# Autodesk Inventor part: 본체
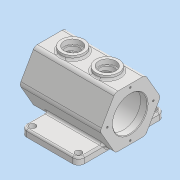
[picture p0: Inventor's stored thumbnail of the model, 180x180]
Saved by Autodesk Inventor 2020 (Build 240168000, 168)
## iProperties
Created: 2021-06
Part Number: 본체
Material: 일반
Document SubType Name: Modeling
Designer: Administrator
Density: 1 g/cm^3
Appearance: 기본값
Author: Administrator
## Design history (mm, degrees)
sketch "스케치1"
  geometry: L1 (52.5, 0)-(26.25, -45.466); L2 (26.25, -45.466)-(-26.25, -45.466); L3 (-26.25, -45.466)-(-52.5, 0); L4 (-52.5, 0)-(-26.25, 45.466); L5 (-26.25, 45.466)-(26.25, 45.466); L6 (26.25, 45.466)-(52.5, 0); 3 further points
  constraints: 12 end point, 1 coincident, 1 midpoint, 1 vertical alignment, 13 other
  dimensions: "d0" = 52.5 distance of L1.start point (0, 0)
extrude "돌출1" new body sketch "스케치1" stored distance "d1" = 140; taper "d2" = 0 deg
node "작업 평면1"
sketch "스케치2"
  geometry: L1 (-45, -75)-(55, -75); L2 (55, -75)-(55, 75); L3 (55, 75)-(-45, 75); L4 (-45, 75)-(-45, -75); L5 (-70, 26.25)-(-70, 52.5) reference; L6 (70, 52.5)-(70, 26.25) reference; 2 further points
  constraints: 8 end point, 2 parallel, 1 horizontal, 1 horizontal alignment, 1 midpoint, 1 perpendicular
  dimensions: "d4" = 150 distance of L1.end L2.end; "d5" = 25 distance between parallel lines of L4 L5; "d6" = 100 distance of L2.end L3.end
extrude "돌출2" join sketch "스케치2" distance "d7" = 12; taper "d8" = 0 deg
sketch "스케치3"
  geometry: L1 (70, 45.466)-(70, 0) reference; L2 (-70, 0)-(-70, 45.466) reference; L3 (70, 30)-(-70, 30); L4 (-70, 30)-(-70, 0); L5 (-70, 0)-(70, 0); L6 (70, 0)-(70, 30); L7 (58, 37.5)-(-58, 37.5); L8 (-58, 37.5)-(-58, 30); L9 (-58, 30)-(58, 30); L10 (58, 30)-(58, 37.5); 6 further points
  constraints: 16 end point, 4 parallel, 3 point on line, 2 horizontal, 2 midpoint, 2 perpendicular, 1 coincident, 1 vertical alignment
  dimensions: "d9" = 60 diameter of L3 L5; "d10" = 75 diameter of L7 L5; "d11" = 12 distance between parallel lines of L10 L1
revolve "회전1" sketch "스케치3" stored, may be unused: angle "d12" = 90 deg
node "작업 평면2"
sketch "스케치4"
  geometry: L1 (-70, -26.25)-(-70, 26.25) reference; C1 r 20 at (-30, 0); C2 r 20 at (30, 0); 1 further point
  constraints: 2 centre point, 2 horizontal alignment, 1 equal radius
  dimensions: "d14" = 40 distance from line of C1.centre L1; "d15" = 60 distance of C2.centre C1.centre; "d16" = 40 diameter of C1
extrude "돌출3" join sketch "스케치4" stored distance "d17" = 52.5; taper "d18" = 0 deg
sketch "스케치5"
  geometry: C1 r 20 at (0, 0) reference; 2 further points
  constraints: 1 coincident
hole "구멍1" sketch "스케치5" at (0, 0) diameter "d19" = 25; stored, may be unused: countersink angle "d23" = 90 deg, drill point angle "d25" = 118 deg; dims "d20" = 6, "d21" = 30, "d22" = 8, "d24" = 8
chamfer "모따기1" distance "d26" = 1; stored, may be unused: second distance "d27" = 2, angle "d28" = 45 deg
fillet "모깎기1" dims "d29" = 10, "d30" = 5, "d38" = 8
sketch "스케치6"
  geometry: A1 r 10 centre (-35, -65) between (-45, -65) and (-35, -75) reference; A2 r 10 centre (45, -65) between (45, -75) and (55, -65) reference; 3 further points
  constraints: 2 coincident
hole "구멍2" sketch "스케치6" at (-35, -65), (45, -65) diameter "d31" = 11; stored, may be unused: countersink angle "d35" = 90 deg, drill point angle "d37" = 118 deg; dims "d32" = 6, "d33" = 30, "d34" = 8, "d36" = 8
fillet "모깎기2" dims "d39" = 3
fillet "모깎기3" dims "d40" = 3
sketch "스케치7"
  geometry: L1 (0, 0)-(0, 40); C1 r 37.5 at (0, 0) reference; A1 r 40 centre (0, 0) between (0, 40) and (-40, 0); 1 further point
  constraints: 2 end point, 2 point on circle, 1 centre point, 1 coincident, 1 horizontal alignment, 1 vertical
  dimensions: "d41" = 80 diameter of A1
hole "구멍3" sketch "스케치7" at (-40, 0) diameter "d43" = 3.242; stored, may be unused: countersink angle "d47" = 90 deg, drill point angle "d49" = 118 deg; dims "d44" = 8, "d45" = 30, "d46" = 8, "d48" = 10
sketch "스케치8"
  geometry: L1 (0, 0)-(0, -40); L2 (0, 0)-(28.284, -28.284); L3 (40, 0)-(-40, 0); C1 r 30 at (0, 0) reference; C2 r 1.621 at (-40, 0) reference; A1 r 40 centre (0, 0) between (28.284, -28.284) and (0, -40); 3 further points
  constraints: 6 end point, 3 point on circle, 2 coincident, 1 centre point, 1 horizontal, 1 symmetric about line, 1 vertical
  dimensions: "d53" = 80 diameter of A1; "d54" = 45 deg angle of L2 L1
hole "구멍4" sketch "스케치8" at (28.284, -28.284), (28.284, 28.284) diameter "d55" = 3.242; stored, may be unused: countersink angle "d59" = 90 deg, drill point angle "d61" = 118 deg; dims "d56" = 8, "d57" = 30, "d58" = 8, "d60" = 10
sketch "스케치9"
  geometry: L1 (-45, 65)-(-45, 32.293) reference; L2 (45, 75)-(-35, 75) reference; 2 further points
  constraints: 1 other
  dimensions: "d65" = 50 distance from line of point (5, 61) L1; "d66" = 14 distance from line of point (5, 61) L2
feature "엠보싱1" sketch "스케치9" dims "d0" = 52.5, "d67" = 0.5, "d68" = 0
sketch "스케치10"
  geometry: L1 (-65, -50)-(65, -50) reference; L2 (65, -50)-(-65, -50) reference; L3 (0, -50)-(-91.329, -50); L4 (-91.329, -50)-(-91.329, 67.217); L5 (-91.329, 67.217)-(0, 67.217); L6 (0, 67.217)-(0, -50); 3 further points
  constraints: 8 end point, 2 parallel, 1 horizontal, 1 midpoint, 1 perpendicular
extrude "돌출4" cut sketch "스케치10" extent not by distance; stored distance "d69" = 70; taper "d70" = 0 deg
node "솔리드1"
mirror "미러1"
mirror "미러2"
pattern_circular "원형 패턴1" dims angle "d51" = 360 deg
mirror "미러3"
feature "A9D066F2-1C7D-4E18-AEED-F7BC21143FA4" dims "d31" = 11, "d32" = 6, "d33" = 30, "d34" = 8, "d35" = 90 deg, "d36" = 8, "d37" = 118 deg
other parameters: "d13" = 52.5
